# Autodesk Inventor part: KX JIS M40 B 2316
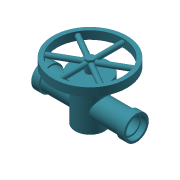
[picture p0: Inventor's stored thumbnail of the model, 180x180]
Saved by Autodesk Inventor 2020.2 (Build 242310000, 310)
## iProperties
Manager: www.cadconsulting.pl
Company: Fabian Stasiak CAD Consulting
IsCustomPart: 0
NAME: PIPING: JIS B 2316 Steel Socket Welding Tee
DATA: <meta><inlinegroups number="1" deflen="6.98"></inlinegroups><connections number="3"></connections><angles><a>3.14159265358979</a><a>1.57079632679489</a></angles
Created: 2014-02
Part Number: KX JIS M40 B 2316
Material: Stal
Description: Zawór M40 B 2316
Document SubType Name: Modeling
Standard: JIS B 2316
Designer: F.Stasiak
Standards Organization: JIS
Language: pl-PL
Size Designation: 40A x Sch80
Categories: <MemberInstance><Categories><Category DisplayName="" InternalName="4347fa0f-2144-441d-94cd-e3e15c92b736" Mnemonic="TUBEANDPIPE"><CategoryParameter DisplayName="
Density: 1 g/cm^3
Appearance: Niebieska z odcieniem szarości
Catalog Web Link: www.expertbooks.pl
Author: F.Stasiak
Subject: Zbiór ćwiczeń. Autodesk Inventor 2020. Kurs Professional
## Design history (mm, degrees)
sketch "Sketch1"
  geometry: L1 (0, 0)-(112.7, 0); L2 (112.7, 0)-(112.7, 26.2); L3 (18.3, 30.15)-(0, 30.15); L4 (0, 24.55)-(0, 0); L5 (12.7, 24.55)-(12.7, 20.6); L6 (12.7, 20.6)-(112.7, 20.6); L7 (18.3, 30.15)-(18.3, 26.2); L8 (18.3, 26.2)-(112.7, 26.2); L9 (0, 24.55)-(0, 30.15); L10 (212.7, 20.6)-(112.7, 20.6); L11 (225.4, 24.55)-(225.4, 30.15); L12 (207.1, 30.15)-(225.4, 30.15); L13 (207.1, 30.15)-(207.1, 26.2); L14 (207.1, 26.2)-(112.7, 26.2); L15 (225.4, 24.55)-(225.4, 0); L16 (225.4, 0)-(112.7, 0); L17 (0, 24.55)-(12.7, 24.55); L18 (225.4, 24.55)-(212.7, 24.55); L19 (212.7, 24.55)-(212.7, 20.6); L20 (0, 24.55)-(0, 0); L21 (0, 0)-(225.4, 0); L22 (225.4, 0)-(225.4, 24.55); C1 r 2.8 at (15.5, 27.35); C2 r 2.8 at (15.5, 23.4)
  constraints: 44 end point, 7 symmetric about line, 7 tangent, 5 perpendicular, 4 parallel, 2 centre point, 2 horizontal, 1 collinear, 1 equal radius, 1 point on line, 9 other
  dimensions: "d0" = 41.2 diameter of L6 L1 (= D); "d1" = 12.7 distance between parallel lines of L9 L5 (= C1); "d2" = 100 distance between parallel lines of L2 L5 (= G); "d6" = 49.1 diameter of L4.start L1 (= S); "d7" = 5.6 distance of L4.start L3.end (= T)
revolve "Revolve1" stored, may be unused: angle "d8" = 90 deg
sketch "Sketch2"
  geometry: L1 (0, 0)-(-112.7, 0) reference; L2 (-112.7, 0)-(-112.7, 62.7); L3 (-112.7, 62.7)-(-152.7, 62.7); L4 (-158.3, 62.7)-(-158.3, 44.4); L5 (-142.7, 0)-(-112.7, 0); L6 (-152.7, 50)-(-142.7, 50); L7 (-142.7, 50)-(-142.7, 0); L8 (-152.7, 62.7)-(-158.3, 62.7); L9 (-158.3, 44.4)-(-148.3, 44.4); L10 (-148.3, 44.4)-(-148.3, 0); L11 (-142.7, 0)-(-148.3, 0); L12 (-152.7, 62.7)-(-152.7, 50); L13 (-152.7, 62.7)-(-112.7, 62.7); L14 (-112.7, 62.7)-(-112.7, 0); L15 (-112.7, 0)-(-142.7, 0); C1 r 2.8 at (-155.5, 47.2); C2 r 2.8 at (-145.5, 47.2)
  constraints: 28 end point, 8 tangent, 6 perpendicular, 2 centre point, 2 parallel, 1 vertical
  dimensions: "d3" = 60 diameter of L7 L2; "d4" = 12.7 distance between parallel lines of L6 L8 (= C1); "d5" = 50 distance between parallel lines of L6 L5 (= 0.5 x G); "d9" = 80 diameter of L3.end L2; "d10" = 5.6 distance of L3.end L4.start (= T)
revolve "Revolve2" stored, may be unused: angle "d18" = 90 deg
revolve "Revolve3" stored, may be unused: angle "d57" = 90 deg
sketch "Szkic8"
  geometry: C1 r 45.6 at (0, 0) reference; C2 r 35.6 at (0, 0) reference; A1 r 35.6 centre (0, 0) between (-24.102, -26.2) and (24.102, -26.2) reference; 1 further point
extrude "Wyciągnięcie proste3" join sketch "Szkic8" distance "d59" = 90; taper "d60" = 0 deg
sketch "Szkic9"
  geometry: C1 r 45.6 at (0, 0) reference; C2 r 10 at (0, 0); 1 further point
  constraints: 1 centre point, 1 coincident
  dimensions: "d61" = 20 diameter of C2
extrude "Wyciągnięcie proste4" join sketch "Szkic9" distance "d62" = 30; taper "d63" = 0 deg
sketch "Szkic10"
  geometry: C1 r 10 at (0, 0) reference; C2 r 10 at (0, 0) reference; C3 r 90 at (0, 0); C4 r 10 at (0, 0) reference; C5 r 80 at (0, 0); 1 further point
  constraints: 2 centre point, 2 coincident
  dimensions: "d64" = 180 diameter of C3; "d65" = 160 diameter of C5
extrude "Wyciągnięcie proste5" join sketch "Szkic10" distance "d66" = 20; taper "d67" = 0 deg
sketch "Szkic11"
  geometry: L1 (-192.7, 92.7)-(-32.7, 92.7) reference; L2 (-32.7, 72.7)-(-192.7, 72.7) reference; L3 (-202.7, 92.7)-(-22.7, 92.7) reference; L4 (-112.7, 92.7)-(-112.7, 72.7); C1 r 6 at (-112.7, 82.7); 1 further point
  constraints: 3 midpoint, 2 end point, 1 centre point
  dimensions: "d68" = 12 diameter of C1
extrude "Wyciągnięcie proste6" join sketch "Szkic11" stored distance "d69" = 175; taper "d70" = 0 deg
pattern_circular "Szyk kołowy1" dims angle "d72" = 360 deg
node "Punkt konstrukcyjny8"
node "Punkt konstrukcyjny9"
node "Oś konstrukcyjna6"
node "Oś konstrukcyjna7"
body "Solid1"
node "Pętla rzutowana1"
node "Pętla rzutowana2"
node "Pętla rzutowana3"
other parameters: "S" = 49.1 [user parameter; used in 1 equation term], "D" = 41.2 [user parameter; used in 1 equation term], "T" = 5.6 [user parameter; used in 2 equation terms], "C1" = 12.7 [user parameter; used in 2 equation terms], "G" = 100 [user parameter; used in 2 equation terms], "Size_Designation" = 12.345 [user parameter]
